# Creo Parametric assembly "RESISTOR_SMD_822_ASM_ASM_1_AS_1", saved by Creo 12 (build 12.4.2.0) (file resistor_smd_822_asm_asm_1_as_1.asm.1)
Units: Custom; MM, KILOGRAM, SECS

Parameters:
  PTC_WM_ITERATION = "0"
  PTC_WM_VERSION = "-.0"
  PTC_WM_LIFECYCLE_STATE = "In Work"
  PTC_WM_LIFECYCLE = "MO_CADDocument"
  PTC_WM_CREATED_BY = "Maximilian Roepper (Z0017RMS: MO)"
  PTC_WM_CREATED_ON = "18-Sep-26 11:36:42 AM"
  PTC_WM_MODIFIED_BY = "Maximilian Roepper (Z0017RMS: MO)"
  PTC_WM_MODIFIED_ON = "18-Sep-26 11:36:46 AM"
  PDMLINKNUMBER = "PDM000071455206"
  PTC_WM_NUMBER = "PDM000071455206"

Other parameters: WEIGHT, WEIGHT_FACTOR, WEIGHT_ADD, MC_ERRORS, SUPPLIER

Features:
  1. coordinate system
  2. imported feature
  3. component "VALOR_PREDETERMINADO_1_PRT_1__1"

Other named items: DRW_VIEW_ORG, ROUGH-GROB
